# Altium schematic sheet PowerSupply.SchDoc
size A4; SheetNumber: 1; SheetTotal: 3
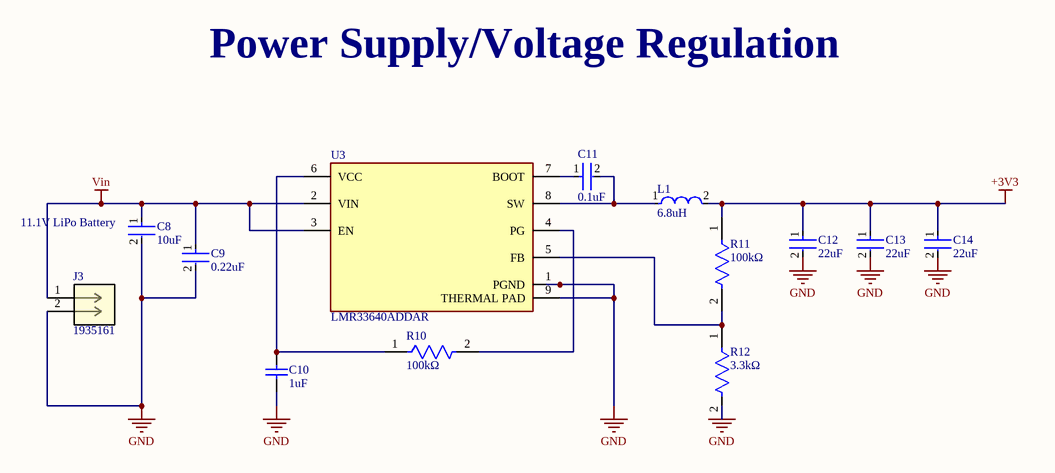
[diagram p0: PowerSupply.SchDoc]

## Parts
C8  10uF  [FP-C0805C-DG-MFG]
C9  0.22uF  [FP-C0603C-CF-MFG]
C10  1uF  [CAPC3216X180X50ML20T25]
C11  0.1uF  [FP-C0805C104M5UACTU-MFG]
C12  22uF  [FP-C3225-250-0_4-IPC_B]
C13  22uF  [FP-C3225-250-0_4-IPC_B]
C14  22uF  [FP-C3225-250-0_4-IPC_B]
J3  1935161  [CONN_1935161_PXC]
L1  6.8uH  [FP-MLZ2012-0_85-IPC_A]
R10  100kΩ  [FP-RMCF0402-IPC_C]
R11  100kΩ  [FP-RMCF0402-IPC_C]
R12  3.3kΩ  [FP-RMCF1210-IPC_A]
U3  LMR33640ADDAR  [FP-DDA0008J-IPC_A]

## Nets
+3V3: C12.1 C13.1 C14.1 L1.2 R11.1
GND: C8.2 C9.2 C10.1 C12.2 C13.2 C14.2 J3.2 R12.2 U3.1(PGND) U3.9(THERMAL_PAD)
Vin: C8.1 C9.1 J3.1 U3.2(VIN) U3.3(EN)
NetC10_2: C10.2 R10.1 U3.6(VCC)
NetC11_1: C11.1 U3.7(BOOT)
NetC11_2: C11.2 L1.1 U3.8(SW)
NetR10_2: R10.2 U3.4(PG)
NetR11_2: R11.2 R12.1 U3.5(FB)

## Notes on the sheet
- Power Supply/Voltage Regulation
- (near C8) 11.1V LiPo Battery

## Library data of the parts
C8 = CMP-2007-03243-2: C0805C106K8PACTU CAP CER 10UF 10V X5R 0805; Manufacturer: Kemet; 3DS Part Number: 220-00001; Tolerance: 10%; Temperature Coefficient: 15%; Material: Ceramic
C9 = CMP-2006-03146-2: C0603C224K3RACTU CAP CER 0.22UF 25V 10% X7R 0603; Manufacturer: KEMET; Temperature Coefficient: 30ppm/°C; Value: 0.22 μF; Material: Ceramic; Tolerance: 0.1; Automotive Grade: Grade 1
C10 = CMP-2000-04991-1: C1206C105K3RACTU Chip Capacitor, 1 uF, +/- 10%, 25 V, -55 to 125 degC, 1206 (3216 Metric), RoHS, Tape and Reel; Manufacturer: Kemet; Temperature Coefficient / Code: +/-15%; Dielectric: X7R; Voltage Rating DC: 25V; Capacitance - nF: 1000nF; Class: Class1; Case Length: 3.2mm; Type: SMDMLCCX7R6.3-250VDCCommericalGrade; Case Width: 1.6mm
C11 = CMP-2007-03742-2: C0805C104M5UACTU CAP CER 0.1UF 50V Z5U 0805; Dielectric Material: Ceramic; Tolerance: 20%; Dissipation Factor: 4%; Capacitance: 100nF
C12-C14 = CMP-2000-06052-2: C3225X7R1C226M250AC Multilayer Ceramic Capacitors 22uF ±20% 16V X7R SMD 1210
J3 = 1935161: Ceramic Capacitor, Multilayer, Ceramic, 16V, 10% +Tol, 10% -Tol, X5R, 15% TC, 10uF, Surface Mount, 0805; Mfr_Name: Phoenix Contact; Manufacturer: Samsung; Manufacturer Part Number: CL21A106KOQNNNE; Multilayer: Yes
L1 = CMP-08253-000092-1: MLZ2012N6R8LT000 Shielded Multilayer Inductor 6.8uH ±20% 550mA 325mΩ SMD 0805; Test Frequency: 2MHz; Self Resonant Frequency: 60MHz; Saturation Current: 110mA; Core Material: Ferrite; DC Resistance (DCR): 250mR
R10 R11 = CMP-2000-06984-2: RMCF0402FT100K 100kΩ ±1% 0.063W 0402 Thick Film Chip Resistor AEC-Q200 compliant; Max Power Dissipation: 63mW; Resistance: 100kR; Temperature Coefficient: 100ppm/°C; Power Rating: 62.5mW
R12 = CMP-26527-001928-1: RMCF1210JT3K30 3.3kΩ ±5% 0.5W 1210 Thick Film Chip Resistor AEC-Q200 compliant; Temperature Coefficient: 200ppm/°C; Resistance: 3.3kR; Max Power Dissipation: 333mW
U3 = CMP-04918-000399-1: 36V 4A 400KHZ REGULATOR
